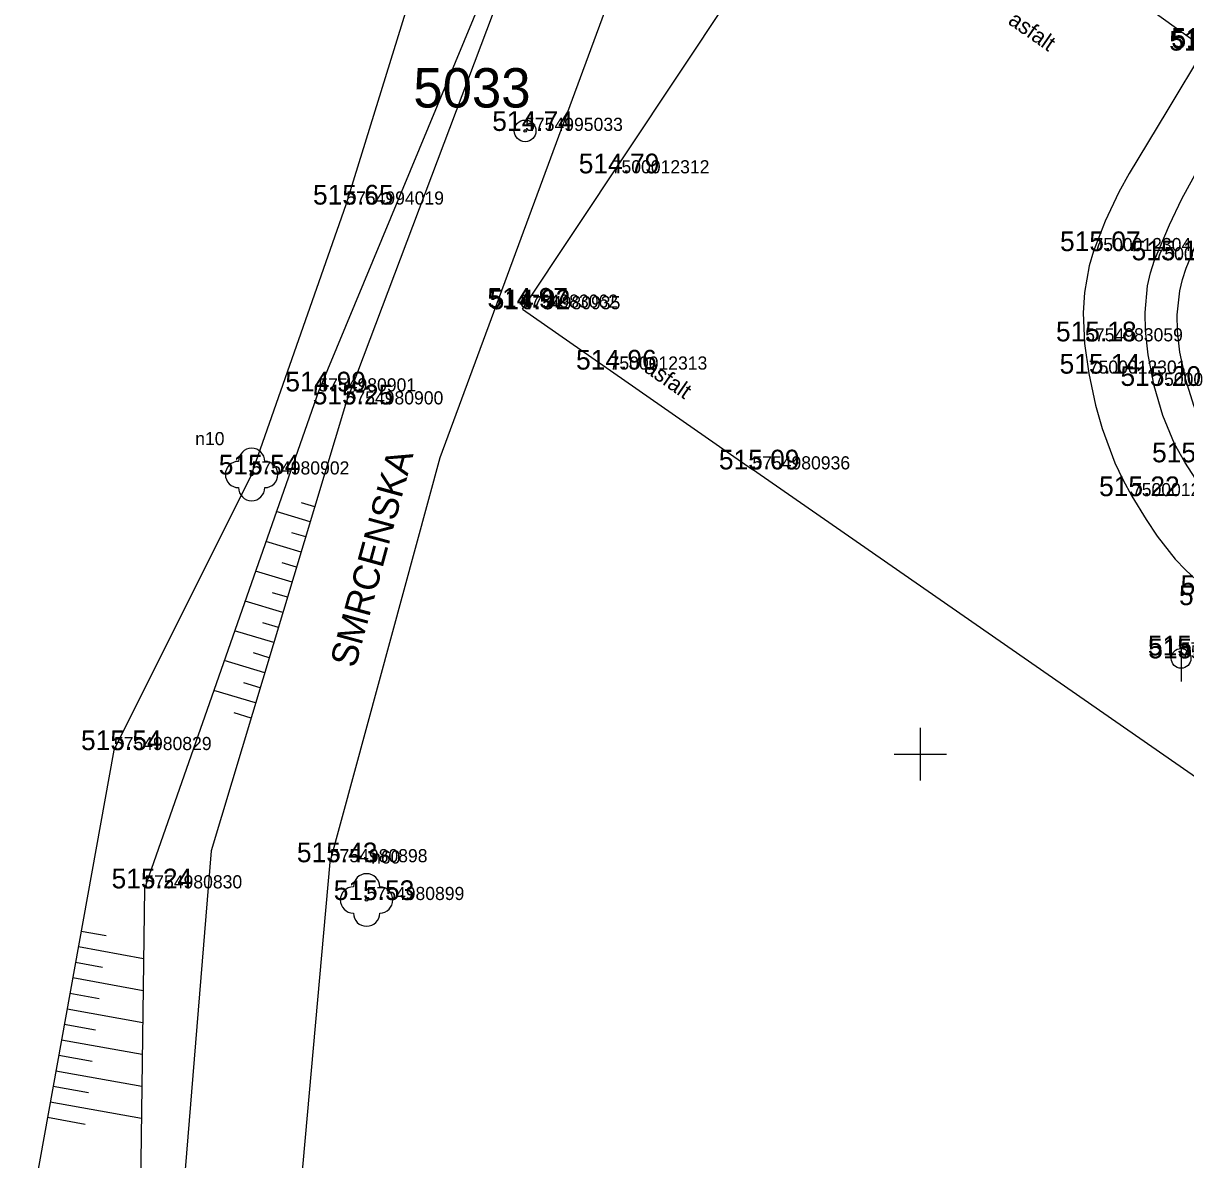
# Model space of a CAD drawing. Extents: x -669251 to -668549, y -1128351 to -1127698.
# Drawn here: x -669034.14 to -668989.9, y -1127965.44 to -1127922.18 of the extents above; entities that cross this region are included whole.
import ezdxf

# ---------------------------------------------------------------- set-up
doc = ezdxf.new("R2010")
doc.units = 0
for name, color, linetype in [('Vrstva 1', 7, 'Continuous'), ('Vrstva 10', 7, 'Continuous'), ('Vrstva 14', 7, 'Continuous'), ('Vrstva 15', 7, 'Continuous'), ('Vrstva 2', 7, 'Continuous'), ('Vrstva 21', 7, 'Continuous'), ('Vrstva 22', 7, 'Continuous'), ('Vrstva 27', 7, 'Continuous'), ('Vrstva 3', 7, 'Continuous'), ('Vrstva 40', 7, 'Continuous'), ('Vrstva 45', 7, 'Continuous'), ('Vrstva 47', 7, 'Continuous'), ('Vrstva 61', 7, 'Continuous'), ('Vrstva 63', 7, 'Continuous')]:
    doc.layers.add(name, color=color, linetype=linetype)

msp = doc.modelspace()

# ---------------------------------------------------------------- linework, layer by layer
at = {"layer": 'Vrstva 1'}
for p, q in [((-669015.036, -1127926.281), (-669015.036, -1127926.281)), ((-669011.742, -1127927.895), (-669011.742, -1127927.895)), ((-669021.843, -1127929.084), (-669021.843, -1127929.084)), ((-668993.409, -1127930.855), (-668993.409, -1127930.855)), ((-668991.084, -1127931.204), (-668991.084, -1127931.204)), ((-669015.22, -1127933.009), (-669015.22, -1127933.009)), ((-669015.133, -1127933.068), (-669015.133, -1127933.068)), ((-668993.726, -1127934.29), (-668993.726, -1127934.29)), ((-669011.823, -1127935.364), (-669011.823, -1127935.364)), ((-668993.589, -1127935.518), (-668993.589, -1127935.518)), ((-668991.095, -1127935.985), (-668991.095, -1127935.985)), ((-669022.904, -1127936.195), (-669022.904, -1127936.195)), ((-669021.868, -1127936.689), (-669021.868, -1127936.689)), ((-669006.389, -1127939.163), (-669006.389, -1127939.163)), ((-668989.928, -1127938.893), (-668989.928, -1127938.893)), ((-669025.444, -1127939.356), (-669025.444, -1127939.356)), ((-668991.945, -1127940.181), (-668991.945, -1127940.181)), ((-668990.088, -1127946.241), (-668990.088, -1127946.241)), ((-668990.074, -1127946.355), (-668990.074, -1127946.355)), ((-669030.685, -1127949.845), (-669030.685, -1127949.845)), ((-669022.47, -1127954.114), (-669022.47, -1127954.114)), ((-669029.522, -1127955.109), (-669029.522, -1127955.109)), ((-669021.069, -1127955.552), (-669021.069, -1127955.552))]:
    msp.add_line(p, q, dxfattribs=at)
at = {"layer": 'Vrstva 10'}
for p, q in [((-669021.868, -1127936.689), (-669009.543, -1127904.044)), ((-669005.568, -1127904.308), (-669018.284, -1127938.726)), ((-668989.186, -1127923.144), (-669002.232, -1127913.78)), ((-669015.133, -1127933.068), (-669006.232, -1127919.676)), ((-669015.133, -1127933.068), (-669006.389, -1127939.163)), ((-669021.868, -1127936.689), (-669026.985, -1127953.677)), ((-669018.284, -1127938.726), (-669022.47, -1127954.114)), ((-668971.728, -1127963.246), (-669006.389, -1127939.163)), ((-669026.985, -1127953.677), (-669028.745, -1127975.23)), ((-669022.47, -1127954.114), (-669024.234, -1127973.832))]:
    msp.add_line(p, q, dxfattribs=at)
for points in [[(-668983.234, -1127944.915), (-668985.02, -1127943.742), (-668986.806, -1127942.569), (-668987.289, -1127942.216), (-668988.048, -1127941.504), (-668988.56, -1127940.905), (-668989.263, -1127939.928), (-668989.928, -1127938.893), (-668990.321, -1127938.191), (-668990.772, -1127937.107), (-668991.095, -1127935.985), (-668991.331, -1127934.796), (-668991.431, -1127933.882), (-668991.447, -1127933.195), (-668991.352, -1127932.18), (-668991.242, -1127931.685), (-668991.084, -1127931.204), (-668990.521, -1127929.853), (-668990.05, -1127928.864), (-668989.264, -1127927.426), (-668988.38, -1127926.048), (-668987.168, -1127924.304), (-668985.955, -1127922.56)], [(-668989.186, -1127923.144), (-668990.618, -1127925.523), (-668992.051, -1127927.902), (-668992.447, -1127928.61), (-668992.965, -1127929.712), (-668993.409, -1127930.855), (-668993.579, -1127931.418), (-668993.756, -1127932.433), (-668993.799, -1127933.208), (-668993.748, -1127934.374), (-668993.589, -1127935.518), (-668993.332, -1127936.717), (-668993.081, -1127937.604), (-668992.591, -1127938.908), (-668992.289, -1127939.549), (-668991.945, -1127940.181), (-668991.41, -1127941.067), (-668990.989, -1127941.7), (-668990.297, -1127942.581), (-668989.913, -1127942.985), (-668989.496, -1127943.36), (-668988.706, -1127944.015), (-668987.916, -1127944.67)]]:
    msp.add_lwpolyline(points, dxfattribs=at)
at = {"layer": 'Vrstva 14'}
for p, q in [((-669021.843, -1127929.084), (-669012.846, -1127899.967)), ((-669009.543, -1127904.044), (-669022.904, -1127936.195)), ((-669025.444, -1127939.356), (-669021.843, -1127929.084)), ((-669022.904, -1127936.195), (-669029.522, -1127955.109)), ((-669025.444, -1127939.356), (-669030.685, -1127949.845)), ((-669030.685, -1127949.845), (-669034.135, -1127968.921)), ((-669029.522, -1127955.109), (-669029.811, -1127977.068))]:
    msp.add_line(p, q, dxfattribs=at)
at = {"layer": 'Vrstva 15'}
for p, q in [((-669023.041, -1127940.584), (-669023.547, -1127940.432)), ((-669023.214, -1127941.159), (-669024.505, -1127940.77)), ((-669023.387, -1127941.733), (-669023.914, -1127941.574)), ((-669023.561, -1127942.308), (-669024.902, -1127941.904)), ((-669023.733, -1127942.882), (-669024.28, -1127942.717)), ((-669023.907, -1127943.457), (-669025.298, -1127943.038)), ((-669024.08, -1127944.031), (-669024.646, -1127943.86)), ((-669024.253, -1127944.606), (-669025.695, -1127944.172)), ((-669024.599, -1127945.755), (-669026.092, -1127945.305)), ((-669024.426, -1127945.18), (-669025.013, -1127945.003)), ((-669024.772, -1127946.329), (-669025.379, -1127946.146)), ((-669024.945, -1127946.904), (-669026.488, -1127946.439)), ((-669025.291, -1127948.053), (-669026.885, -1127947.573)), ((-669025.118, -1127947.478), (-669025.745, -1127947.289)), ((-669025.464, -1127948.627), (-669026.112, -1127948.432)), ((-669031.931, -1127956.734), (-669030.978, -1127956.907)), ((-669032.038, -1127957.325), (-669029.557, -1127957.773)), ((-669032.145, -1127957.915), (-669031.113, -1127958.102)), ((-669032.251, -1127958.506), (-669029.573, -1127958.99)), ((-669032.358, -1127959.096), (-669031.247, -1127959.297)), ((-669032.465, -1127959.687), (-669029.589, -1127960.207)), ((-669032.572, -1127960.276), (-669031.382, -1127960.492)), ((-669032.678, -1127960.868), (-669029.605, -1127961.423)), ((-669032.785, -1127961.457), (-669031.516, -1127961.687)), ((-669032.892, -1127962.048), (-669029.621, -1127962.64)), ((-669032.999, -1127962.639), (-669031.651, -1127962.882)), ((-669033.105, -1127963.229), (-669029.637, -1127963.856)), ((-669033.212, -1127963.82), (-669031.785, -1127964.078))]:
    msp.add_line(p, q, dxfattribs=at)
at = {"layer": 'Vrstva 21'}
msp.add_lwpolyline([(-668988.405, -1127939.023), (-668988.648, -1127938.646), (-668988.887, -1127938.265), (-668989.212, -1127937.671), (-668989.593, -1127936.727), (-668989.894, -1127935.755), (-668990.129, -1127934.704), (-668990.218, -1127933.891), (-668990.226, -1127933.278), (-668990.129, -1127932.371), (-668990.027, -1127931.93), (-668989.885, -1127931.501), (-668989.357, -1127930.236), (-668988.916, -1127929.31), (-668988.18, -1127927.962), (-668987.352, -1127926.672), (-668986.161, -1127924.958), (-668984.984, -1127923.265)], dxfattribs=at)
at = {"layer": 'Vrstva 22'}
for centre in [(-669025.444, -1127939.356), (-669021.07, -1127955.55)]:
    msp.add_circle(centre, 0.05, dxfattribs=at)
for centre, start, end in [((-669025.444, -1127938.856), 0, 180), ((-669025.944, -1127939.356), 90, 270), ((-669024.944, -1127939.356), 270, 90), ((-669025.444, -1127939.856), 180, 0), ((-669021.07, -1127955.05), 0, 180), ((-669021.57, -1127955.55), 90, 270), ((-669020.57, -1127955.55), 270, 90), ((-669021.07, -1127956.05), 180, 0)]:
    msp.add_arc(centre, 0.5, start, end, dxfattribs=at)
at = {"layer": 'Vrstva 27'}
msp.add_line((-668990.074, -1127945.98), (-668990.074, -1127947.23), dxfattribs=at)
msp.add_circle((-668990.074, -1127946.355), 0.375, dxfattribs=at)
at = {"layer": 'Vrstva 61'}
for p, q in [((-669000, -1127949), (-669000, -1127951)), ((-669001, -1127950), (-668999, -1127950))]:
    msp.add_line(p, q, dxfattribs=at)
at = {"layer": 'Vrstva 63'}
for radius in [0.412, 0.412, 0.05, 0.05]:
    msp.add_circle((-669015.036, -1127926.281), radius, dxfattribs=at)

# ---------------------------------------------------------------- texts
at = {"layer": 'Vrstva 2'}
for s, p in [('5754995033', (-669015.036, -1127926.281)), ('7500012312', (-669011.742, -1127927.895)), ('5754994019', (-669021.843, -1127929.084)), ('7500012304', (-668993.409, -1127930.855)), ('7500012305', (-668991.084, -1127931.204)), ('5754983062', (-669015.22, -1127933.009)), ('5754980935', (-669015.133, -1127933.068)), ('5754983059', (-668993.726, -1127934.29)), ('7500012313', (-669011.823, -1127935.364)), ('7500012301', (-668993.589, -1127935.518)), ('7500012300', (-668991.095, -1127935.985)), ('5754980901', (-669022.904, -1127936.195)), ('5754980900', (-669021.868, -1127936.689)), ('5754980936', (-669006.389, -1127939.163)), ('5754980902', (-669025.444, -1127939.356)), ('7500012303', (-668991.945, -1127940.181)), ('5754983057', (-668990.088, -1127946.241)), ('7500012296', (-668990.074, -1127946.355)), ('5754980829', (-669030.685, -1127949.845)), ('5754980898', (-669022.47, -1127954.114)), ('5754980830', (-669029.522, -1127955.109)), ('5754980899', (-669021.069, -1127955.552))]:
    msp.add_text(s, height=0.5, dxfattribs=at).set_placement(p)
at = {"layer": 'Vrstva 3'}
for s, p in [('514.89 ', (-668990.45, -1127923.112)), ('514.95 ', (-668990.44, -1127923.144)), ('514.95 ', (-668990.526, -1127923.223)), ('514.74 ', (-669016.288, -1127926.281)), ('514.79 ', (-669012.997, -1127927.895)), ('515.65 ', (-669023.109, -1127929.084)), ('515.07 ', (-668994.683, -1127930.855)), ('515.11 ', (-668991.958, -1127931.204)), ('514.97 ', (-669016.474, -1127933.009)), ('514.92 ', (-669016.387, -1127933.068)), ('515.18 ', (-668994.836, -1127934.29)), ('514.96 ', (-669013.099, -1127935.364)), ('515.14 ', (-668994.699, -1127935.518)), ('515.20 ', (-668992.383, -1127935.985)), ('514.99 ', (-669024.161, -1127936.195)), ('515.25 ', (-669023.12, -1127936.689)), ('515.24 ', (-668991.18, -1127938.893)), ('515.54 ', (-669026.696, -1127939.356)), ('515.09 ', (-669007.665, -1127939.163)), ('515.22 ', (-668993.197, -1127940.181)), ('515.38 ', (-668990.093, -1127943.945)), ('515.15 ', (-668990.155, -1127944.328)), ('515.34 ', (-668991.34, -1127946.241)), ('515.27 ', (-668991.326, -1127946.355)), ('515.54 ', (-669031.937, -1127949.845)), ('515.43 ', (-669023.722, -1127954.114)), ('515.24 ', (-669030.774, -1127955.109)), ('515.53 ', (-669022.321, -1127955.552))]:
    msp.add_text(s, height=0.75, dxfattribs=at).set_placement(p)
at = {"layer": 'Vrstva 40'}
for rotation, p in [(325.136, (-668996.697, -1127922.178)), (325.1216, (-669010.548, -1127935.411))]:
    msp.add_text('asfalt', height=0.6, rotation=rotation, dxfattribs=at).set_placement(p)
at = {"layer": 'Vrstva 45'}
msp.add_text('SMRCENSKA', height=1, rotation=74.7821, dxfattribs=at).set_placement((-669021.504, -1127946.751))
at = {"layer": 'Vrstva 47'}
for s, height, p in [('n10', 0.5, (-669027.592, -1127938.24)), ('n60', 0.499, (-669020.898, -1127954.164))]:
    msp.add_text(s, height=height, dxfattribs=at).set_placement(p)
at = {"layer": 'Vrstva 63'}
msp.add_text('5033', height=1.5, dxfattribs=at).set_placement((-669019.292, -1127925.391))
msp.add_text('5033', height=1.5, dxfattribs=at).set_placement((-669019.292, -1127925.391))

doc.saveas('drawing.dxf')
